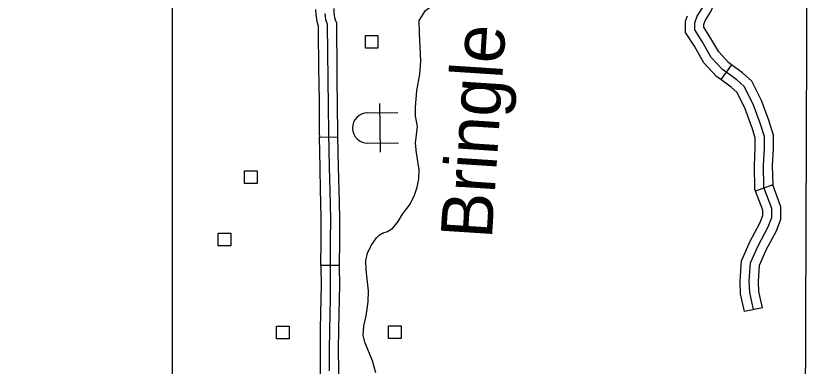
# Model space of a CAD drawing. Extents: x -19 to 366, y -4 to 359.
# Drawn here: x 131.239 to 132.483, y 200.288 to 200.833 of the extents above; entities that cross this region are included whole.
import ezdxf

# ---------------------------------------------------------------- set-up
doc = ezdxf.new("R2010")
doc.units = 0
for name, color, linetype in [('21', 7, 'Continuous'), ('60', 7, 'Continuous'), ('R_Axis Annot', 7, 'Continuous'), ('R_ROW', 7, 'Continuous'), ('R_Temp Easement', 7, 'Continuous'), ('Sheet Fence', 7, 'Continuous'), ('T_Indications', 7, 'Continuous')]:
    doc.layers.add(name, color=color, linetype=linetype)

msp = doc.modelspace()

# ---------------------------------------------------------------- linework, layer by layer
at = {"layer": '21'}
for points in [[(131.7828, 200.7827), (131.7828, 200.8024), (131.8025, 200.8024), (131.8025, 200.7827)], [(131.5945, 200.5716), (131.5945, 200.5913), (131.6143, 200.5913), (131.6143, 200.5716)], [(131.5535, 200.4747), (131.5535, 200.4944), (131.5733, 200.4944), (131.5733, 200.4747)], [(131.6444, 200.3299), (131.6444, 200.3497), (131.6642, 200.3497), (131.6642, 200.3299)], [(131.8187, 200.3306), (131.8187, 200.3503), (131.8385, 200.3503), (131.8385, 200.3306)]]:
    msp.add_lwpolyline(points, close=True, dxfattribs=at)
at = {"layer": '60'}
for p, q in [((131.8048, 200.6964), (131.806, 200.6206)), ((131.7861, 200.6819), (131.8334, 200.6826)), ((131.7869, 200.6345), (131.8342, 200.6353))]:
    msp.add_line(p, q, dxfattribs=at)
msp.add_arc((131.7865, 200.6582), 0.0237, 90.9307, 270.9307, dxfattribs=at)
at = {"layer": 'R_Axis Annot'}
for points in [[(132.4676, 200.0674), (132.4715, 201.0786)], [(131.4826, 200.0645), (131.4827, 201.0664)]]:
    msp.add_lwpolyline(points, dxfattribs=at)
at = {"layer": 'R_ROW'}
for p, q in [((131.7112, 200.6437), (131.7396, 200.6444)), ((131.742, 200.444), (131.7136, 200.4442))]:
    msp.add_line(p, q, dxfattribs=at)
for points in [[(131.7051, 200.8426), (131.7056, 200.8351), (131.707, 200.8239), (131.7092, 200.8173), (131.7094, 200.8168), (131.7101, 200.7439)], [(131.7335, 200.8444), (131.7339, 200.8378), (131.7348, 200.8303), (131.736, 200.8269), (131.7378, 200.8221), (131.7385, 200.7442)], [(131.7197, 200.8364), (131.7209, 200.8271), (131.7226, 200.8221), (131.7236, 200.8195), (131.7244, 200.7338), (131.7249, 200.6927), (131.7252, 200.6504), (131.7265, 200.5973), (131.7273, 200.5603), (131.7283, 200.5156), (131.7281, 200.4831), (131.7278, 200.4405), (131.7281, 200.4149), (131.7278, 200.3919), (131.7274, 200.3694), (131.7264, 200.314), (131.7266, 200.2799)], [(131.7101, 200.7439), (131.7102, 200.7337), (131.7107, 200.6926), (131.711, 200.6502), (131.7112, 200.6437)], [(131.7385, 200.7442), (131.7386, 200.734), (131.7391, 200.6928), (131.7394, 200.6506), (131.7396, 200.6444)], [(131.7135, 200.5438), (131.7131, 200.56), (131.7123, 200.597), (131.7112, 200.6437)], [(131.7396, 200.6444), (131.7407, 200.5976), (131.7415, 200.5606), (131.7419, 200.5444)], [(131.7136, 200.4442), (131.7139, 200.4832), (131.7141, 200.5155), (131.7135, 200.5438)], [(131.7419, 200.5444), (131.7425, 200.5157), (131.7423, 200.483), (131.742, 200.444)], [(131.7136, 200.4442), (131.7135, 200.4405), (131.7139, 200.4149), (131.7136, 200.3921), (131.7132, 200.3697), (131.7127, 200.3443)], [(131.742, 200.444), (131.742, 200.4406), (131.7423, 200.415), (131.742, 200.3916), (131.7416, 200.3692), (131.7411, 200.3439)], [(131.7127, 200.3443), (131.7122, 200.3141), (131.7124, 200.2799), (131.7123, 200.2442)], [(131.7411, 200.3439), (131.7406, 200.314), (131.7408, 200.2799), (131.7407, 200.244)]]:
    msp.add_lwpolyline(points, dxfattribs=at)
at = {"layer": 'R_Temp Easement'}
for points in [[(131.8666, 200.8258), (131.8766, 200.841), (131.8898, 200.8513), (131.9129, 200.8987), (131.9207, 200.9117), (131.9314, 200.9259), (131.9479, 200.9416), (131.9542, 200.9451), (131.9739, 200.9492), (131.9851, 200.9554), (131.9903, 200.9608), (132.0025, 201.0069), (132.0031, 201.0191), (131.9974, 201.0417), (131.9876, 201.067), (131.9844, 201.0799), (131.9837, 201.0977), (131.9749, 201.1279), (131.9724, 201.1415), (131.9741, 201.1567), (131.981, 201.1758), (131.9895, 201.1877), (131.9951, 201.1976), (131.9966, 201.2041)], [(131.7993, 200.2767), (131.7937, 200.2956), (131.7819, 200.3246), (131.7794, 200.3352), (131.7804, 200.35), (131.7839, 200.3656), (131.7874, 200.3873), (131.7875, 200.4048), (131.7843, 200.4373), (131.7837, 200.4521), (131.7862, 200.4635), (131.7921, 200.475), (131.8002, 200.4873), (131.8043, 200.4911), (131.8107, 200.495), (131.8175, 200.497), (131.8257, 200.5024), (131.8339, 200.5124), (131.8405, 200.5239), (131.8524, 200.5396), (131.8594, 200.5537), (131.8634, 200.5663), (131.8662, 200.5792), (131.8664, 200.5929), (131.8622, 200.6194), (131.8608, 200.6346), (131.8638, 200.6608), (131.8609, 200.6767), (131.8607, 200.6903), (131.863, 200.7165), (131.8679, 200.7413), (131.8691, 200.7625), (131.8669, 200.8057), (131.8666, 200.8258)]]:
    msp.add_lwpolyline(points, dxfattribs=at)
at = {"layer": 'Sheet Fence'}
for points in [[(139.4406, 1.5315), (139.2511, 10.1473), (139.0608, 18.7633), (138.8699, 27.3793), (138.6784, 35.9956), (138.4861, 44.6119), (138.2932, 53.2285), (138.0997, 61.8451), (137.9055, 70.4619), (137.7106, 79.0789), (137.5151, 87.6959), (137.319, 96.3132), (137.1221, 104.9306), (136.9247, 113.5481), (136.7265, 122.1658), (136.5278, 130.7836), (136.3283, 139.4016), (136.1282, 148.0197), (135.9275, 156.6379), (135.7261, 165.2564), (135.5241, 173.8749), (135.3214, 182.4936), (135.1181, 191.1125), (134.9141, 199.7315), (134.7095, 208.3506), (134.5043, 216.9699), (134.2984, 225.5894), (134.0919, 234.209), (133.8847, 242.8288), (133.6769, 251.4487), (133.4685, 260.0687), (133.2594, 268.6889), (133.0497, 277.3093), (132.8393, 285.9298), (132.6283, 294.5504), (132.4167, 303.1713), (132.2044, 311.7922), (131.9916, 320.4133), (131.778, 329.0346), (131.5639, 337.656), (131.3491, 346.2776)], [(132.1027, 1.3746), (131.9232, 9.99), (131.7429, 18.6056), (131.5621, 27.2214), (131.3806, 35.8373), (131.1985, 44.4533), (131.0158, 53.0695), (130.8324, 61.6859), (130.6485, 70.3024), (130.4639, 78.919), (130.2786, 87.5358), (130.0928, 96.1527), (129.9063, 104.7698), (129.7193, 113.387), (129.5316, 122.0044), (129.3433, 130.6219), (129.1543, 139.2396), (128.9648, 147.8575), (128.7746, 156.4754), (128.5838, 165.0936), (128.3925, 173.7119), (128.2005, 182.3303), (128.0078, 190.9489), (127.8146, 199.5676), (127.6208, 208.1865), (127.4264, 216.8056), (127.2313, 225.4247), (127.0357, 234.0441), (126.8394, 242.6636), (126.6425, 251.2833), (126.4451, 259.9031), (126.247, 268.523), (126.0483, 277.1431), (125.849, 285.7634), (125.6492, 294.3838), (125.4487, 303.0044), (125.2476, 311.6252), (125.0459, 320.2461), (124.8437, 328.8671), (124.6408, 337.4883), (124.4373, 346.1097)], [(0, 198.1326), (7.1014, 198.137), (14.2028, 198.1503), (21.3042, 198.1724), (28.4055, 198.2034), (35.5068, 198.2433), (42.6081, 198.292), (49.7092, 198.3496), (56.8103, 198.4161), (63.9113, 198.4913), (71.0123, 198.5755), (78.1131, 198.6685), (85.2137, 198.7704), (92.3143, 198.8811), (99.4147, 199.0007), (106.5149, 199.1291), (113.615, 199.2664), (120.7149, 199.4126), (127.8146, 199.5676), (134.9141, 199.7315), (142.0135, 199.9042), (149.1125, 200.0858), (156.2114, 200.2762), (163.31, 200.4755), (170.4084, 200.6837), (177.5065, 200.9007), (184.6043, 201.1265), (191.7018, 201.3612), (198.799, 201.6048), (205.896, 201.8572), (212.9926, 202.1185), (220.0888, 202.3886), (227.1848, 202.6676), (234.2803, 202.9554), (241.3755, 203.2521), (248.4704, 203.5576), (255.5648, 203.872), (262.6589, 204.1952), (269.7525, 204.5273), (276.8457, 204.8682), (283.9385, 205.218), (291.0309, 205.5766), (298.1228, 205.9441), (305.2142, 206.3204), (312.3051, 206.7056), (319.3956, 207.0996), (326.4856, 207.5024), (333.5751, 207.9141), (340.664, 208.3347)]]:
    msp.add_spline(points, degree=3, dxfattribs=at)
at = {"layer": 'T_Indications'}
for p, q in [((132.3532, 200.7565), (132.3364, 200.7337)), ((132.4171, 200.5699), (132.3905, 200.56)), ((132.4011, 200.3784), (132.3733, 200.3723))]:
    msp.add_line(p, q, dxfattribs=at)
for points in [[(132.3109, 200.8227), (132.3122, 200.8261), (132.3203, 200.8386), (132.3262, 200.8511), (132.3338, 200.8631), (132.3373, 200.8837), (132.3325, 200.9044), (132.3325, 200.9209)], [(132.3872, 200.3753), (132.3813, 200.402), (132.3807, 200.4195), (132.3826, 200.4481), (132.3943, 200.4748), (132.4099, 200.5041), (132.4158, 200.519), (132.4158, 200.5327), (132.4034, 200.5658), (132.4028, 200.6003), (132.4041, 200.6263), (132.4041, 200.6452), (132.3982, 200.664), (132.3865, 200.6953), (132.3729, 200.7226), (132.3612, 200.733), (132.3391, 200.7493), (132.3215, 200.7682), (132.3072, 200.7929), (132.2956, 200.8111), (132.2956, 200.8221), (132.2994, 200.8325), (132.3079, 200.8455)], [(132.3364, 200.7337), (132.3296, 200.7386), (132.3101, 200.7596), (132.2951, 200.7855), (132.2813, 200.8069), (132.2813, 200.8247), (132.2843, 200.8327)], [(132.3532, 200.7565), (132.3486, 200.7599), (132.333, 200.7767), (132.3194, 200.8003), (132.3098, 200.8152), (132.3098, 200.8196), (132.3109, 200.8227)], [(132.4118, 200.6683), (132.4117, 200.6687), (132.3996, 200.7009), (132.3844, 200.7314), (132.3701, 200.7441), (132.3532, 200.7565)], [(132.3848, 200.6594), (132.3735, 200.6896), (132.3614, 200.7138), (132.3522, 200.722), (132.3364, 200.7337)], [(132.4176, 200.5685), (132.417, 200.6001), (132.4183, 200.626), (132.4183, 200.6473), (132.4118, 200.6682)], [(132.3905, 200.56), (132.3893, 200.5632), (132.3886, 200.6005), (132.3899, 200.6267), (132.3899, 200.643), (132.3847, 200.6598)], [(132.4063, 200.4667), (132.4071, 200.4686), (132.4229, 200.4981), (132.43, 200.5163), (132.43, 200.5352), (132.4171, 200.5699)], [(132.3803, 200.4781), (132.3816, 200.481), (132.397, 200.51), (132.4016, 200.5217), (132.4016, 200.5301), (132.3905, 200.56)], [(132.3733, 200.3723), (132.3672, 200.4002), (132.3665, 200.4198), (132.3686, 200.4516), (132.3803, 200.4781)], [(132.4011, 200.3784), (132.3955, 200.4038), (132.3949, 200.4193), (132.3966, 200.4447), (132.4063, 200.4667)]]:
    msp.add_lwpolyline(points, dxfattribs=at)

# ---------------------------------------------------------------- texts
at = {"layer": 'R_Temp Easement'}
msp.add_text('Bringle', height=0.08, rotation=86.2628, dxfattribs=at).set_placement((131.9797, 200.4844))

doc.saveas('drawing.dxf')
